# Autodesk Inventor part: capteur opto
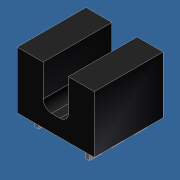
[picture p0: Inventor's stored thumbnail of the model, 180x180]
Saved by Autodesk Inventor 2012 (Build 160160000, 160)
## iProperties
Created: 2011-10
Part Number: capteur opto
Material: Nylon - 6/6
Document SubType Name: Modeling
Designer: Laur
Mass: 0.0578537 g
Surface Area: 1.09315 cm^2
Volume: 0.0511979 cm^3
Density: 1.13 g/cm^3
Author: Laur
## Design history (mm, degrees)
sketch "Esquisse1"
  geometry: L1 (13.326, 5.17)-(13.326, 0.52) reference; L2 (12.826, 0.02)-(10.776, 0.02) reference; L3 (10.276, 0.52)-(10.276, 5.17) reference; L4 (10.776, 5.67)-(12.826, 5.67) reference; L5 (-3.613, 12.119)-(-3.613, 7.319) reference; L6 (-4.113, 6.819)-(-16.713, 6.819) reference; L7 (-16.713, 6.819)-(-16.713, -8.877) reference; L8 (-16.272, -10.13)-(-14.837, -11.914) reference; L9 (-12.613, -11.131)-(-12.613, -4.381) reference; L10 (-12.113, -3.881)-(9.987, -3.881) reference; L11 (10.487, -4.381)-(10.487, -4.681) reference; L12 (10.987, -5.181)-(11.237, -5.181) reference; L13 (11.737, -5.681)-(11.737, -6.981) reference; L14 (11.237, -7.481)-(10.487, -7.481) reference; L15 (10.487, -7.481)-(10.487, -12.381) reference; L16 (10.487, -12.381)-(13.587, -12.381) reference; L17 (15.587, -10.381)-(15.587, 6.819) reference; L18 (15.587, 6.819)-(14.887, 6.819) reference; L19 (14.387, 7.319)-(14.387, 9.434) reference; L20 (14.267, 9.759)-(11.537, 12.944) reference; L21 (11.157, 13.119)-(-2.613, 13.119) reference; L22 (-2.613, 13.119)-(-3.613, 12.119) reference; L23 (-10.913, 0.819)-(-15.513, 0.819); L24 (-15.513, 0.819)-(-15.513, 4.919); L25 (-15.513, 4.919)-(-10.913, 4.919); L26 (-10.913, 4.919)-(-10.913, 0.819); L27 (-14.456, 4.919)-(-14.456, 0.819); L28 (-12.606, 4.919)-(-12.606, 0.819); C1 r 1.075 at (-9.144, 5.136) reference; C2 r 1.075 at (7.356, -2.064) reference; A1 r 0.5 centre (12.826, 0.52) between (12.826, 0.02) and (13.326, 0.52) reference; A2 r 0.5 centre (10.776, 0.52) between (10.276, 0.52) and (10.776, 0.02) reference; A3 r 0.5 centre (10.776, 5.17) between (10.776, 5.67) and (10.276, 5.17) reference; A4 r 0.5 centre (12.826, 5.17) between (13.326, 5.17) and (12.826, 5.67) reference; A5 r 0.5 centre (-4.113, 7.319) between (-4.113, 6.819) and (-3.613, 7.319) reference; A6 r 2 centre (-14.713, -8.877) between (-16.713, -8.877) and (-16.272, -10.13) reference; A7 r 1.25 centre (-13.863, -11.131) between (-14.837, -11.914) and (-12.613, -11.131) reference; A8 r 0.5 centre (-12.113, -4.381) between (-12.113, -3.881) and (-12.613, -4.381) reference; A9 r 0.5 centre (9.987, -4.381) between (10.487, -4.381) and (9.987, -3.881) reference; A10 r 0.5 centre (10.987, -4.681) between (10.487, -4.681) and (10.987, -5.181) reference; A11 r 0.5 centre (11.237, -5.681) between (11.737, -5.681) and (11.237, -5.181) reference; A12 r 0.5 centre (11.237, -6.981) between (11.237, -7.481) and (11.737, -6.981) reference; A13 r 2 centre (13.587, -10.381) between (13.587, -12.381) and (15.587, -10.381) reference; A14 r 0.5 centre (14.887, 7.319) between (14.387, 7.319) and (14.887, 6.819) reference; A15 r 0.5 centre (13.887, 9.434) between (14.387, 9.434) and (14.267, 9.759) reference; A16 r 0.5 centre (11.157, 12.619) between (11.537, 12.944) and (11.157, 13.119) reference
  constraints: 12 end point, 4 point on line, 3 perpendicular, 2 parallel, 1 horizontal
  dimensions: "d0" = 4.6 distance between parallel lines of L26 L24; "d1" = 4.1 distance between parallel lines of L25 L23; "d2" = 1.2 distance between parallel lines of L24 L7; "d3" = 1.9 distance between parallel lines of L6 L25
extrude "base" new body sketch "Esquisse1" distance "d4" = 1; taper "d5" = 0 deg
sketch "Esquisse2"
  geometry: L1 (-10.913, 0.819)-(-15.513, 0.819) reference; L2 (-10.913, 4.919)-(-10.913, 0.819) reference; L3 (-15.513, 4.919)-(-10.913, 4.919) reference; L4 (-15.513, 0.819)-(-15.513, 4.919) reference; L5 (-13.963, 4.919)-(-13.963, 0.819); L6 (-12.463, 4.919)-(-12.463, 0.819)
  constraints: 4 end point, 4 point on line, 2 perpendicular
  dimensions: "d6" = 1.5 distance between parallel lines of L6 L5; "d7" = 1.55 distance between parallel lines of L4 L5 (computed from d6)
extrude "fourche" join sketch "Esquisse2" distance "d8" = 2.4; taper "d9" = 0 deg
fillet "Congé1" dims "d10" = 0.5, "d11" = 0.5
sketch "Esquisse3"
  geometry: L1 (12.113, 3.334)-(11.891, 3.334); L2 (11.891, 3.334)-(11.891, 2.632); L3 (11.891, 2.632)-(12.113, 2.632); L4 (12.113, 2.632)-(12.113, 3.334); L5 (12.103, 4.711)-(11.88, 4.711); L6 (11.88, 4.711)-(11.88, 4.009); L7 (11.88, 4.009)-(12.103, 4.009); L8 (12.103, 4.009)-(12.103, 4.711); L9 (12.11, 2.013)-(11.887, 2.013); L10 (11.887, 2.013)-(11.887, 1.311); L11 (11.887, 1.311)-(12.11, 1.311); L12 (12.11, 1.311)-(12.11, 2.013); L13 (15.256, 2.122)-(15.034, 2.122); L14 (15.034, 2.122)-(15.034, 1.42); L15 (15.034, 1.42)-(15.256, 1.42); L16 (15.256, 1.42)-(15.256, 2.122); L17 (15.206, 4.543)-(14.983, 4.543); L18 (14.983, 4.543)-(14.983, 3.841); L19 (14.983, 3.841)-(15.206, 3.841); L20 (15.206, 3.841)-(15.206, 4.543)
  constraints: 40 end point, 10 parallel, 5 horizontal, 5 perpendicular
node "Plan de construction1"
extrude "5 pattes" join sketch "Esquisse3" distance "d12" = 1.5; taper "d13" = 0 deg
node "Solide1"
node "Corps solides"
node "Corps surfaciques"
node "Référence1"
